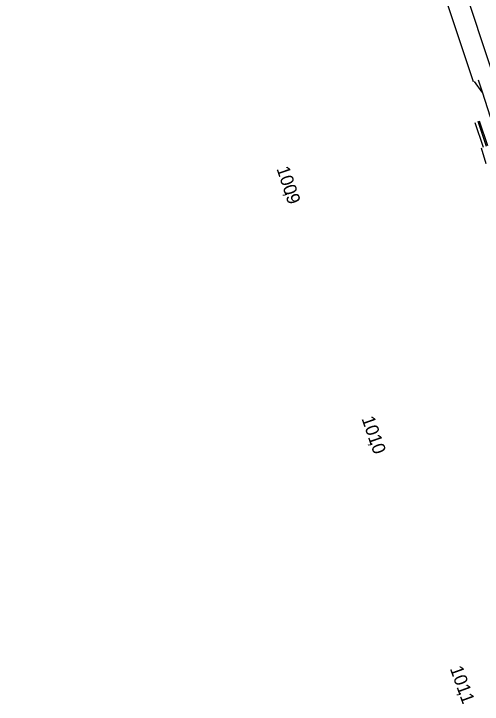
# Model space of a CAD drawing. Extents: x -678487 to -674601, y -1104811 to -1093295.
# Drawn here: x -677219.1 to -677039.7, y -1097874.8 to -1097610.5 of the extents above; entities that cross this region are included whole.
import ezdxf

# ---------------------------------------------------------------- set-up
doc = ezdxf.new("R2010")
doc.units = 0
for name, color, linetype in [('00_MiNGO', 7, 'Continuous'), ('SOxxxxxx_Osa_bod_P', 7, 'Continuous'), ('SOxxxxxx_Staničení_Popis', 7, 'Continuous'), ('SOxxxxxx_ŽSp_hrana', 7, 'Continuous'), ('SOxxxxxx_ŽSp_násyp_hrana', 7, 'Continuous'), ('SOxxxxxx_ŽSp_odvodnění', 7, 'Continuous'), ('SOxxxxxx_ŽSp_zářez_hrana', 7, 'Continuous')]:
    doc.layers.add(name, color=color, linetype=linetype)

msp = doc.modelspace()

# ---------------------------------------------------------------- linework, layer by layer
at = {"layer": '00_MiNGO'}
for radius in [8494.25, 8510.25]:
    msp.add_arc((-668968.6, -1094948.57), radius, 197.933224, 198.41166, dxfattribs=at)
at = {"layer": 'SOxxxxxx_Osa_bod_P'}
msp.add_arc((-668968.6, -1094948.57), 8502.25, 183.991255, 200.113006, dxfattribs=at)
at = {"layer": 'SOxxxxxx_ŽSp_hrana'}
for p, q in [((-677041.33, -1097635.84), (-677039.8, -1097640.42)), ((-677039.8, -1097640.42), (-677036.63, -1097649.91))]:
    msp.add_line(p, q, dxfattribs=at)
at = {"layer": 'SOxxxxxx_ŽSp_násyp_hrana'}
msp.add_line((-677042.75, -1097636.36), (-677039.93, -1097640.46), dxfattribs=at)
at = {"layer": 'SOxxxxxx_ŽSp_odvodnění'}
for p, q in [((-677041.37, -1097651.66), (-677038.18, -1097661.15)), ((-677040.85, -1097651.47), (-677037.67, -1097660.96))]:
    msp.add_line(p, q, dxfattribs=at)
at = {"layer": 'SOxxxxxx_ŽSp_zářez_hrana'}
for p, q in [((-677042.54, -1097652.09), (-677039.38, -1097661.6)), ((-677040.09, -1097661.86), (-677038.39, -1097667.86))]:
    msp.add_line(p, q, dxfattribs=at)

# ---------------------------------------------------------------- texts
at = {"layer": 'SOxxxxxx_Staničení_Popis'}
for s, rotation, p in [('100', 288.5105, (-677118.56, -1097669.76)), (',', 288.5105, (-677115.53, -1097678.82)), ('9', 288.5105, (-677115.02, -1097680.33)), ('101', 289.1844, (-677085.99, -1097765.43)), (',', 289.1844, (-677082.85, -1097774.46)), ('0', 289.1844, (-677082.33, -1097775.97)), ('101', 289.8583, (-677052.17, -1097861.08)), (',', 289.8583, (-677048.92, -1097870.06)), ('1', 289.8583, (-677048.38, -1097871.56))]:
    msp.add_text(s, height=5, rotation=rotation, dxfattribs=at).set_placement(p)

doc.saveas('drawing.dxf')
